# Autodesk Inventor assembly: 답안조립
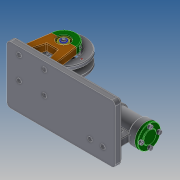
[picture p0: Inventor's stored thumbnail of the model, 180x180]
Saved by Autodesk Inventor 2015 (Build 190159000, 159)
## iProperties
Created: 2018-01
Part Number: 답안조립
Document SubType Name: Assembly
Designer: SCD-A03
Mass: 865.836 g
Surface Area: 888.145 cm^2
Volume: 224.243 cm^3
Density: 3.86116 g/cm^3
Author: SCD-A03
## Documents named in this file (19)
- C:\Users\SCD-A03\Desktop\380108V1008\답안조립.iam
- C:\Users\SCD-A03\Desktop\380108V1008\플레이트.ipt
- C:\Users\SCD-A03\Desktop\380108V1008\3mm 와셔.ipt
- C:\Users\SCD-A03\Desktop\380108V1008\V-벨트풀리.ipt
- C:\Users\SCD-A03\Desktop\380108V1008\둥근머리볼트 M3x12.ipt
- C:\Users\SCD-A03\Desktop\380108V1008\베어링 8x22x7.ipt
- C:\Users\SCD-A03\Desktop\380108V1008\베어링커버-A.ipt
- C:\Users\SCD-A03\Desktop\380108V1008\볼트 M3x8.ipt
- C:\Users\SCD-A03\Desktop\380108V1008\볼트 M3x12.ipt
- C:\Users\SCD-A03\Desktop\380108V1008\스페이서.ipt
- C:\Users\SCD-A03\Desktop\380108V1008\지지대-A.ipt
- C:\Users\SCD-A03\Desktop\380108V1008\커넥팅로드-A.ipt
- C:\Users\SCD-A03\Desktop\380108V1008\커넥팅로드-B.ipt
- C:\Users\SCD-A03\Desktop\380108V1008\크랭크축.ipt
- C:\Users\SCD-A03\Desktop\380108V1008\플랜지.ipt
- C:\Users\SCD-A03\Desktop\380108V1008\피스톤.ipt
- C:\Users\SCD-A03\Desktop\380108V1008\하우징.ipt
- C:\Users\SCD-A03\Desktop\380108V1008\하우징커버-A.ipt
- C:\Users\SCD-A03\Desktop\380108V1008\하우징커버-B.ipt
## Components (9 placed, 8 different names)
1. 플레이트:1 — 각도:3
2. 3mm 와셔:1
3. V-벨트풀리:1 — 각도:3
4. 플랜지:1
5. 피스톤:1
6. 하우징:1
7. 하우징커버-A:1
8. 하우징커버-B:1
9. 3mm 와셔:2
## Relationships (1: Angle 1)
- 각도:3 [Angle]: 플레이트:1 ↔ V-벨트풀리:1
